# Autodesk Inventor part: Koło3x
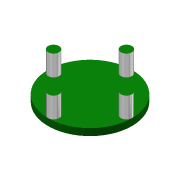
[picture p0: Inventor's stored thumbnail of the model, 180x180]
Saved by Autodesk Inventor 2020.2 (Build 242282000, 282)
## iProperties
Created: 2005-10
Part Number: Koło3x
Document SubType Name: Modeling
Designer: F.Stasiak
Density: 1 g/cm^3
Material: Ogólny
Appearance: Ciemnozielona
Manager: www.cadconsulting.pl
Company: Fabian Stasiak CAD Consulting
Author: F.Stasiak
Subject: Zbiór ćwiczeń. Autodesk Inventor 2020. Kurs podstawowy
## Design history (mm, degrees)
sketch "Szkic1"
  geometry: C1 r 30.5 at (0, 0); 1 further point
  constraints: 1 centre point, 1 coincident
  dimensions: "d0" = 61 diameter of C1
extrude "Wyciągnięcie proste1" new body sketch "Szkic1" distance "d1" = 5; taper "d2" = 0 deg
sketch "Szkic2"
  geometry: C1 r 30.5 at (0, 0) reference; C2 r 4 at (26.5, 0)
  constraints: 1 centre point, 1 tangent
  dimensions: "d3" = 8 diameter of C2
extrude "Wyciągnięcie proste2" join sketch "Szkic2" distance "d4" = 15; taper "d5" = 0 deg
sketch "Szkic3"
  geometry: C1 r 30.5 at (0, 0) reference; C2 r 10 at (0, 0)
  constraints: 1 centre point, 1 coincident
  dimensions: "d6" = 20 diameter of C2
extrude "Wyciągnięcie proste3" join sketch "Szkic3" distance "d7" = 5; taper "d8" = 0 deg
pattern_circular "Szyk kołowy1" dims angle "d10" = 360 deg
node "Bryła1"
node "Korpusy bryłowe"
node "Korpusy powierzchniowe"
